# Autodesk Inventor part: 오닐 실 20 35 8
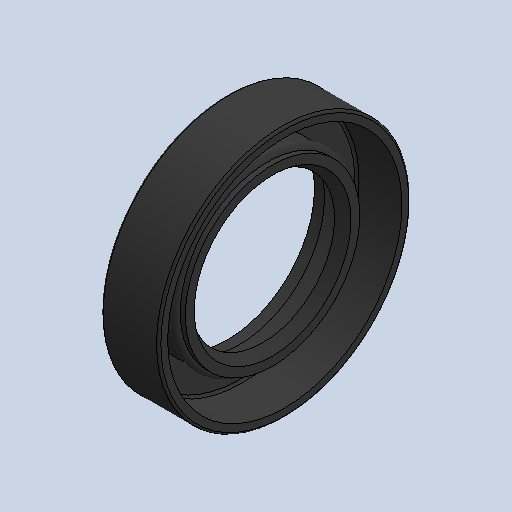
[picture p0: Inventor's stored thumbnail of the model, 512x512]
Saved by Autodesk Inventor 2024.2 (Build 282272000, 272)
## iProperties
Created: 2025-09
Part Number: 오닐 실 20 35 8
Material: 고무
Description: 오일-실
Document SubType Name: Modeling
Designer: home
Density: 0.93 g/cm^3
Appearance: 기본값
Author: jhkim
Sending System: Autodesk Inventor 2026
Preprocessor: ST-DEVELOPER v20.1
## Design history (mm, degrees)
feature "Solid1"
node "솔리드1"
